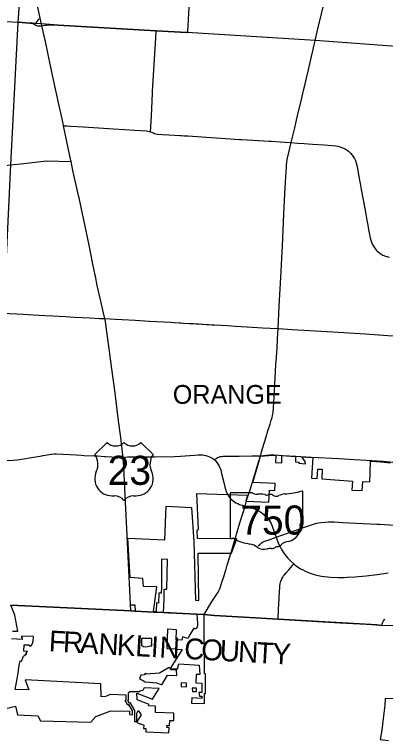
# Model space of a CAD drawing. Extents: x 1729596 to 1925846, y 659247 to 911751.
# Drawn here: x 1818365 to 1836127, y 772469 to 807237 of the extents above; entities that cross this region are included whole.
import ezdxf

# ---------------------------------------------------------------- set-up
doc = ezdxf.new("R2010")
doc.units = 0
for name, color, linetype in [('GM_X_Adjacent_County_Text', 7, 'Continuous'), ('GM_X_City_Street', 7, 'Continuous'), ('GM_X_Corporation', 7, 'Continuous'), ('GM_X_County', 7, 'Continuous'), ('GM_X_County_Road', 7, 'Continuous'), ('GM_X_State_Route', 7, 'Continuous'), ('GM_X_State_Shield', 7, 'Continuous'), ('GM_X_Township', 7, 'Continuous'), ('GM_X_Township_Road', 7, 'Continuous'), ('GM_X_Township_Text', 7, 'Continuous'), ('GM_X_US_Route', 7, 'Continuous'), ('GM_X_US_Shield', 7, 'Continuous')]:
    doc.layers.add(name, color=color, linetype=linetype)

msp = doc.modelspace()

# ---------------------------------------------------------------- linework, layer by layer
at = {"layer": 'GM_X_City_Street'}
for points in [[(1829157, 782891), (1829157, 782893), (1829284, 783295), (1829370, 783578), (1829403, 783698)], [(1829403, 783698), (1829476, 783942)], [(1828738, 781474), (1828935, 782130), (1829157, 782891)], [(1830888, 782204), (1832249, 782689), (1832627, 782818), (1832829, 782872), (1833025, 782905), (1833227, 782932), (1833389, 782939), (1833673, 782939), (1834091, 782912), (1835705, 782831)], [(1835705, 782831), (1835839, 782824), (1836553, 782786), (1836955, 782764), (1837100, 782758), (1837765, 782732)], [(1830028, 781790), (1830127, 781875), (1830195, 781928), (1830278, 781977), (1830355, 782013), (1830512, 782069), (1830888, 782204)], [(1830981, 778275), (1830981, 778426), (1830998, 778636), (1831007, 778800), (1831013, 778930), (1831036, 779338), (1831048, 779591), (1831061, 779791), (1831069, 779893), (1831081, 779966), (1831097, 780033), (1831121, 780106), (1831168, 780218), (1831205, 780288), (1831244, 780348), (1831278, 780391), (1831372, 780495), (1831514, 780657), (1831665, 780837), (1831734, 780922)], [(1827440, 778500), (1827802, 779087), (1828113, 779577), (1828183, 779692), (1828216, 779780), (1828313, 780101), (1828381, 780311), (1828487, 780643), (1828494, 780666)], [(1823936, 778682), (1823966, 778677), (1824145, 778671)], [(1825505, 778597), (1825506, 778597), (1825736, 778586), (1825825, 778586), (1826422, 778555), (1827074, 778521)], [(1827074, 778521), (1827092, 778520), (1827440, 778500)], [(1827440, 778500), (1827947, 778461), (1830173, 778324)], [(1830173, 778324), (1830981, 778275), (1833959, 778105)], [(1835956, 777979), (1835975, 778062), (1835994, 778131), (1836010, 778170), (1836027, 778201), (1836056, 778247), (1836092, 778281)], [(1833959, 778105), (1834906, 778051)], [(1834906, 778051), (1835221, 778034)], [(1835221, 778034), (1835694, 778007)], [(1835694, 778007), (1835717, 778005), (1835956, 777979)]]:
    msp.add_lwpolyline(points, dxfattribs=at)
at = {"layer": 'GM_X_Corporation'}
for points in [[(1818267, 777712), (1818526, 777699), (1818382, 778477), (1818182, 778957), (1823932, 778674), (1823918, 778971), (1824127, 778960), (1824141, 778666), (1825025, 778622), (1825481, 778599), (1825506, 778597), (1825523, 779224), (1825533, 779720), (1825651, 779713), (1825692, 781132), (1825397, 781147), (1825395, 779815), (1825387, 779525), (1825271, 779527), (1825258, 779053), (1825157, 779059), (1825145, 778634), (1825026, 778639), (1825182, 779821), (1824534, 779849), (1824515, 780220), (1823897, 780274), (1823795, 782165), (1825564, 782072), (1825620, 783690), (1826843, 783626), (1826946, 782000), (1827027, 779186), (1827198, 779170), (1827151, 781435), (1828757, 781433), (1829006, 782129), (1827128, 782148), (1827107, 782565), (1827182, 782566), (1827094, 784298), (1829525, 784216), (1829446, 783938), (1830547, 783879), (1830576, 784449), (1830831, 784435), (1830843, 784770), (1829780, 784830), (1830014, 785633), (1830149, 786086), (1830738, 786138), (1830880, 786128), (1830868, 785781), (1831158, 785769), (1831166, 786112), (1831819, 786077), (1831815, 785806), (1831974, 785799), (1831974, 785747), (1832303, 785711), (1832283, 785826), (1832129, 786061), (1832652, 786025), (1832587, 785037), (1832862, 785017), (1832886, 785468), (1833103, 785455), (1833079, 785005), (1834553, 784895), (1834518, 784462), (1835014, 784440), (1835039, 784870), (1835370, 784853), (1835392, 785285), (1835406, 785847), (1835905, 785817), (1836363, 785772)], [(1817968, 774000), (1818411, 774114), (1818508, 773703), (1819478, 773652), (1819605, 773412), (1822027, 773351), (1822253, 773619), (1822982, 773891), (1823867, 773865), (1823869, 773706), (1824013, 773704), (1824009, 773883), (1823832, 774190), (1823788, 774165), (1823663, 774381), (1823707, 774406), (1823707, 774642), (1822967, 774677), (1822717, 774575), (1822517, 774567), (1822492, 775187), (1818880, 775374), (1819053, 774896), (1818404, 774908), (1818486, 775425), (1818535, 775710), (1818583, 776065), (1818636, 776280), (1818700, 776269), (1818798, 776499), (1818958, 776635), (1818908, 776636), (1818992, 776737), (1818809, 776740), (1818820, 777055), (1819068, 777042), (1819068, 777007), (1819165, 777003), (1819223, 777108), (1819253, 777229), (1819268, 777456), (1818703, 777466), (1818702, 777396), (1818737, 777395), (1818738, 777311), (1818223, 777335)], [(1836587, 774459), (1836117, 774478), (1836103, 774163), (1836034, 773645), (1835958, 772968), (1835872, 772517), (1836265, 772469)]]:
    msp.add_lwpolyline(points, dxfattribs=at)
for points in [[(1824345, 775442), (1824627, 775281), (1825175, 775235), (1825413, 775126), (1825685, 775591), (1826129, 775580), (1826126, 775849), (1825830, 775846), (1825867, 775906), (1826173, 775897), (1826228, 776137), (1827210, 776079), (1827238, 775627), (1827055, 775635), (1827043, 775226), (1827330, 775211), (1827337, 774761), (1827196, 774766), (1827218, 774598), (1827327, 774593), (1827332, 774484), (1826851, 774504), (1826841, 774261), (1827466, 774237), (1827464, 774716), (1827514, 774716), (1827510, 775666), (1827460, 775665), (1827440, 778500), (1827098, 778520), (1827121, 778076), (1827120, 777980), (1827107, 777918), (1827081, 777867), (1827042, 777801), (1826956, 777852), (1826782, 777559), (1826660, 777355), (1826409, 777430), (1826380, 777271), (1826098, 777288), (1826124, 777772), (1825694, 777807), (1825650, 776871), (1826109, 776852), (1826109, 776842), (1826395, 776822), (1825819, 775914), (1825776, 775965), (1825313, 775697), (1824665, 775637), (1824635, 775689), (1824578, 775607), (1824414, 775592)], [(1824442, 777348), (1824442, 777026), (1824494, 776994), (1824548, 776966), (1824656, 776953), (1824740, 776974), (1824853, 776996), (1824934, 777003), (1824934, 777124), (1824922, 777124), (1824922, 777172), (1824942, 777172), (1824942, 777248), (1824942, 777348)], [(1826345, 775056), (1826603, 775041), (1826601, 775212), (1826347, 775231)], [(1823775, 774388), (1823850, 774258), (1823893, 774283), (1824116, 773897), (1824117, 773370), (1824217, 773370), (1824216, 773770), (1824292, 773900), (1824434, 773692), (1824210, 773349), (1824358, 773262), (1824368, 773274), (1824549, 773200), (1824547, 773047), (1824647, 773046), (1824645, 772890), (1825759, 772839), (1825774, 773090), (1825665, 773097), (1825671, 773197), (1825780, 773190), (1825795, 773428), (1825995, 773423), (1825999, 773780), (1825120, 773801), (1825121, 774119), (1824773, 774122), (1824817, 774196), (1824236, 774422), (1824220, 774734), (1824970, 774444), (1825290, 774965), (1824574, 774985), (1824507, 774863), (1824348, 774835), (1824349, 774792), (1823893, 774792), (1823807, 774742), (1823807, 774406)], [(1826873, 774982), (1826880, 774820), (1827079, 774810), (1827071, 774971)]]:
    msp.add_lwpolyline(points, close=True, dxfattribs=at)
at = {"layer": 'GM_X_County'}
msp.add_lwpolyline([(1836651, 777955), (1835956, 777979), (1835717, 778005), (1830981, 778275), (1827947, 778461), (1827440, 778500), (1827092, 778520), (1826422, 778555), (1825825, 778586), (1825736, 778586), (1825506, 778597), (1825481, 778599), (1825025, 778622), (1824141, 778666), (1823966, 778677), (1823936, 778682), (1818187, 778957)], dxfattribs=at)
at = {"layer": 'GM_X_County_Road'}
for points in [[(1797153, 808138), (1797813, 808094), (1798478, 808064), (1798746, 808039), (1801838, 807850), (1803855, 807737), (1803954, 807731), (1804251, 807713), (1804397, 807702), (1804736, 807682), (1805136, 807661), (1806811, 807563), (1808119, 807486), (1809547, 807399), (1810973, 807310), (1811477, 807276), (1812106, 807251), (1812390, 807244), (1812704, 807223), (1813792, 807154), (1815652, 807028), (1817412, 806933), (1818544, 806864), (1818913, 806840)], [(1832766, 805999), (1832958, 806827), (1832968, 806868), (1833153, 807676)], [(1818913, 806840), (1819101, 806829), (1819232, 806820), (1819275, 806791), (1819333, 806753), (1819390, 806722), (1819467, 806700), (1819559, 806690), (1819676, 806703)], [(1831618, 801105), (1831725, 801561), (1831782, 801810), (1831838, 802029), (1831953, 802532), (1832071, 803028), (1832169, 803448), (1832199, 803580), (1832422, 804522), (1832586, 805234), (1832650, 805492), (1832684, 805641), (1832763, 805986), (1832766, 805999)], [(1820717, 801905), (1820738, 801905), (1820881, 801901), (1821048, 801890), (1821670, 801851), (1823103, 801757), (1823630, 801723), (1824118, 801695), (1824691, 801661), (1824752, 801655), (1824814, 801642), (1824880, 801622), (1824978, 801581), (1825016, 801565), (1825065, 801542), (1825127, 801522), (1825213, 801507), (1825442, 801493), (1825753, 801476), (1826274, 801446), (1826357, 801438), (1826504, 801432), (1826669, 801422), (1829143, 801256), (1829167, 801255), (1829247, 801250), (1830557, 801174), (1830565, 801173), (1830661, 801169), (1831088, 801139), (1831565, 801111), (1831618, 801105)], [(1830137, 786102), (1830243, 786458), (1830418, 787013), (1830501, 787304), (1830611, 787617), (1830657, 787812), (1830695, 787936), (1830724, 788026), (1830738, 788091), (1830747, 788159), (1830783, 788662), (1830811, 789171), (1830832, 789527), (1830864, 790126), (1830879, 790499), (1830888, 790614), (1830935, 791259), (1830959, 791695), (1830989, 792193), (1831044, 793262), (1831126, 794929), (1831177, 795880), (1831189, 796127), (1831208, 796535), (1831224, 796892), (1831260, 797697), (1831329, 798960), (1831359, 799467), (1831386, 799918), (1831394, 800046), (1831401, 800130), (1831406, 800170), (1831427, 800290), (1831618, 801105)], [(1831618, 801105), (1831914, 801083), (1832241, 801060), (1832630, 801030), (1833198, 800989), (1833568, 800963), (1833750, 800945), (1833841, 800929), (1833953, 800901), (1833994, 800888), (1834075, 800856), (1834194, 800797), (1834287, 800738), (1834352, 800690), (1834449, 800601), (1834514, 800523), (1834576, 800442), (1834637, 800335), (1834686, 800241), (1834720, 800133), (1834770, 799952), (1834842, 799561), (1834917, 799142), (1834969, 798857), (1835136, 797945), (1835185, 797674), (1835238, 797383), (1835280, 797146), (1835320, 796934), (1835392, 796543), (1835422, 796431), (1835496, 796238), (1835581, 796090), (1835702, 795941), (1835860, 795804), (1836005, 795717), (1836126, 795665), (1836296, 795616)], [(1814566, 799659), (1814662, 799670), (1814940, 799695), (1815216, 799728), (1816018, 799800), (1816744, 799881), (1817764, 799993), (1818194, 800042), (1818804, 800110)], [(1818804, 800110), (1819351, 800171), (1819913, 800231), (1821077, 800198)], [(1830137, 786102), (1830408, 786127), (1830473, 786131), (1830595, 786143), (1830674, 786150), (1830727, 786150), (1830805, 786149), (1831205, 786125), (1831840, 786089), (1832575, 786043), (1833895, 785967), (1834638, 785924), (1835200, 785890), (1836012, 785840), (1836343, 785821), (1836473, 785802), (1836589, 785781), (1836648, 785764), (1836710, 785745), (1836767, 785724)], [(1827933, 785912), (1827967, 785947), (1828014, 785981), (1828077, 786017), (1828143, 786045), (1828212, 786066), (1828234, 786070), (1828276, 786074), (1828349, 786080), (1828458, 786082), (1829120, 786088), (1829721, 786095), (1830137, 786102)], [(1829476, 783942), (1829480, 783955), (1829642, 784477), (1829865, 785207), (1829995, 785632), (1830137, 786102)], [(1828494, 780666), (1828554, 780858), (1828738, 781474)]]:
    msp.add_lwpolyline(points, dxfattribs=at)
at = {"layer": 'GM_X_State_Route'}
for points in [[(1815949, 786077), (1816340, 786036), (1817421, 785936), (1817504, 785931), (1817524, 785929), (1818089, 785876), (1818484, 785913), (1818908, 785967), (1819089, 785999), (1819665, 786100), (1819718, 786112), (1820036, 786168), (1820128, 786185), (1820241, 786200), (1820367, 786198), (1820698, 786179), (1821320, 786143), (1821549, 786130)], [(1821549, 786130), (1821693, 786122), (1822187, 786100), (1822334, 786095)], [(1823563, 786025), (1823628, 786033), (1823775, 786046), (1823922, 786053), (1824581, 786061), (1825105, 786055), (1826030, 786067), (1826319, 786087), (1826985, 786136), (1827143, 786145), (1827249, 786149), (1827367, 786145), (1827524, 786120), (1827661, 786077), (1827737, 786044), (1827810, 786003), (1827879, 785955), (1827933, 785912), (1827993, 785854), (1828049, 785790), (1828123, 785685), (1828168, 785604), (1828202, 785526), (1828238, 785425), (1828282, 785261), (1828387, 784818), (1828437, 784614), (1828504, 784396), (1828565, 784270)], [(1822334, 786095), (1822671, 786075), (1822720, 786071), (1823334, 786043), (1823500, 786028), (1823563, 786025)], [(1828565, 784270), (1828569, 784262), (1828604, 784194), (1828648, 784129), (1828708, 784059), (1828761, 784007), (1828819, 783958), (1828895, 783902), (1828967, 783858), (1829063, 783811), (1829136, 783778), (1829258, 783733), (1829403, 783698)], [(1829403, 783698), (1829636, 783627), (1829774, 783588), (1829890, 783548), (1830017, 783494), (1830110, 783438), (1830211, 783374), (1830305, 783298), (1830422, 783188), (1830516, 783076), (1830564, 783014), (1830648, 782859), (1830699, 782739), (1830797, 782459), (1830888, 782204), (1831011, 781894), (1831061, 781782), (1831130, 781649), (1831230, 781480), (1831303, 781382), (1831449, 781200), (1831590, 781057), (1831734, 780922), (1831852, 780832), (1832062, 780696), (1832163, 780638), (1832275, 780576), (1832437, 780506), (1832565, 780463), (1832716, 780413), (1832906, 780365), (1833062, 780340), (1833344, 780306), (1833500, 780298), (1833859, 780281), (1834130, 780274), (1834309, 780283), (1834652, 780302), (1835197, 780361), (1835722, 780425), (1836249, 780492)]]:
    msp.add_lwpolyline(points, dxfattribs=at)
at = {"layer": 'GM_X_State_Shield'}
for p, q in [((1832171, 783277), (1832171, 784383)), ((1832171, 783277), (1832171, 784383)), ((1828691, 784294), (1828691, 782181)), ((1828691, 784294), (1828691, 782181)), ((1829744, 784330), (1828725, 784330)), ((1829744, 784330), (1828725, 784330)), ((1832171, 783277), (1832171, 783277)), ((1832171, 783277), (1832171, 783277))]:
    msp.add_line(p, q, dxfattribs=at)
for centre, major_axis, start_param, end_param in [((1830931, 787211), (3691, 0), 4.814394, 5.042369), ((1830931, 787211), (3691, 0), 4.814394, 5.042369), ((1832132, 784387), (38.7, 0), 6.141152, 7.989035), ((1832132, 784387), (38.7, 0), 6.141152, 7.989035), ((1828730, 784298), (40.3, 0), 1.712693, 3.28349), ((1828730, 784298), (40.3, 0), 1.712693, 3.28349), ((1829987, 784576), (391, 0), 4.042523, 4.731795), ((1829987, 784576), (391, 0), 4.042523, 4.731795), ((1830116, 783144), (1404, 0), 1.404758, 1.657858), ((1830116, 783144), (1404, 0), 1.404758, 1.657858), ((1830435, 784309), (113, 0), 3.836095, 5.185415), ((1830435, 784309), (113, 0), 3.836095, 5.185415), ((1830601, 784065), (235, 0), 0.950623, 2.079405), ((1830601, 784065), (235, 0), 0.950623, 2.079405), ((1830904, 784400), (282, 0), 4.081561, 5.145723), ((1830904, 784400), (282, 0), 4.081561, 5.145723), ((1831402, 783685), (743, 0), 1.699011, 2.107814), ((1831402, 783685), (743, 0), 1.699011, 2.107814), ((1832162, 783196), (60, 0), 1.883978, 3.671073), ((1832162, 783196), (60, 0), 1.883978, 3.671073), ((1831781, 783056), (360, 0), 5.934695, 6.695948), ((1831781, 783056), (360, 0), 5.934695, 6.695948), ((1832130, 783273), (41.5, 0), 5.05454, 6.418171), ((1832130, 783273), (41.5, 0), 5.05454, 6.418171), ((1831138, 782674), (923, 0), 5.101752, 6.440018), ((1831138, 782674), (923, 0), 5.101752, 6.440018), ((1832310, 782815), (262, 0), 2.387724, 3.262537), ((1832310, 782815), (262, 0), 2.387724, 3.262537), ((1828731, 782176), (40.7, 0), 3.00124, 4.508301), ((1828731, 782176), (40.7, 0), 3.00124, 4.508301), ((1828737, 782392), (310, 0), 4.665946, 4.897461), ((1828737, 782392), (310, 0), 4.665946, 4.897461), ((1828800, 782059), (112, 0), 0.519207, 1.627899), ((1828800, 782059), (112, 0), 0.519207, 1.627899), ((1830214, 783957), (2665, 0), 4.195997, 4.488961), ((1830214, 783957), (2665, 0), 4.195997, 4.488961), ((1831527, 781587), (506, 0), 1.647645, 2.488434), ((1831527, 781587), (506, 0), 1.647645, 2.488434), ((1829419, 781231), (834, 0), 0.823519, 1.323587), ((1829419, 781231), (834, 0), 0.823519, 1.323587), ((1830321, 782048), (529, 0), 4.026481, 4.996735), ((1830321, 782048), (529, 0), 4.026481, 4.996735), ((1830627, 781318), (435, 0), 1.495662, 1.94098), ((1830627, 781318), (435, 0), 1.495662, 1.94098), ((1830665, 781890), (282, 0), 4.691044, 5.507374), ((1830665, 781890), (282, 0), 4.691044, 5.507374), ((1830920, 781685), (79.4, 0), 1.147584, 2.315152), ((1830920, 781685), (79.4, 0), 1.147584, 2.315152), ((1830887, 781976), (298, 0), 4.937069, 5.64225), ((1830887, 781976), (298, 0), 4.937069, 5.64225)]:
    msp.add_ellipse(centre, major_axis=major_axis, ratio=0.8, start_param=start_param, end_param=end_param, dxfattribs=at)
at = {"layer": 'GM_X_Township'}
for points in [[(1845296, 807619), (1845145, 805182), (1843287, 805303), (1843103, 805315), (1843041, 805313), (1842837, 805328), (1840812, 805456), (1837716, 805633), (1832763, 805986), (1831742, 806059), (1826634, 806376), (1826602, 806370), (1825150, 806460), (1820453, 806733), (1819657, 806793), (1819325, 806814), (1819232, 806820), (1819101, 806829), (1818544, 806864), (1818726, 809558)], [(1817250, 778977), (1817281, 779754), (1817338, 781221), (1817524, 785929), (1817856, 792932), (1818194, 800042), (1818544, 806864)]]:
    msp.add_lwpolyline(points, dxfattribs=at)
at = {"layer": 'GM_X_Township_Road'}
for points in [[(1826634, 806376), (1826663, 806429), (1826736, 807853), (1826739, 807902), (1826741, 807936), (1826878, 810126), (1826891, 810353), (1826913, 810774), (1826943, 811293)], [(1819232, 806820), (1819325, 806814), (1819371, 806824), (1819399, 806846), (1819491, 806962), (1819552, 807038)], [(1819676, 806703), (1819803, 806721), (1819894, 806734), (1820004, 806746), (1820092, 806749), (1820453, 806733), (1825150, 806460), (1826602, 806370), (1826634, 806376)], [(1824880, 801622), (1824918, 802376), (1824972, 803474), (1824977, 803552), (1825131, 806119), (1825150, 806460)], [(1817878, 792931), (1817995, 792928), (1818106, 792923), (1818482, 792901), (1818787, 792885), (1819262, 792857), (1819834, 792826), (1820206, 792804), (1820486, 792789), (1820816, 792770), (1821218, 792749), (1821979, 792708), (1822434, 792685), (1822684, 792674)], [(1822684, 792674), (1823205, 792644), (1823518, 792626), (1824136, 792597), (1824824, 792554), (1825845, 792496), (1826005, 792489), (1826266, 792474), (1826340, 792468)], [(1826340, 792468), (1826440, 792462), (1826727, 792446), (1826941, 792432), (1827053, 792426), (1827196, 792418), (1827337, 792408), (1827375, 792407), (1827561, 792395), (1827672, 792389), (1827796, 792381), (1827938, 792372), (1828578, 792339), (1828925, 792317), (1829210, 792298), (1829505, 792285), (1830238, 792237), (1830989, 792193)], [(1830989, 792193), (1830989, 792193), (1831659, 792153), (1833599, 792034), (1835168, 791938), (1836243, 791862), (1837317, 791801), (1838966, 791703), (1839258, 791696)], [(1824145, 778671), (1824181, 778670), (1825025, 778622), (1825481, 778599), (1825505, 778597)]]:
    msp.add_lwpolyline(points, dxfattribs=at)
at = {"layer": 'GM_X_US_Route'}
for points in [[(1819598, 807070), (1819046, 809639), (1818948, 810127), (1818889, 810378), (1818800, 810798), (1818772, 810948)], [(1819959, 805403), (1819958, 805406), (1819845, 805945), (1819676, 806703), (1819657, 806793), (1819598, 807070)], [(1820693, 802007), (1820673, 802094), (1820517, 802807), (1820343, 803596), (1820201, 804258), (1819959, 805403)], [(1821066, 800249), (1820717, 801905), (1820693, 802007)], [(1821461, 798452), (1821449, 798511), (1821155, 799766), (1821077, 800198), (1821066, 800249)], [(1823552, 786128), (1823460, 786981), (1823349, 787775), (1823161, 789237), (1823026, 790261), (1822930, 790991), (1822896, 791248), (1822775, 792154), (1822731, 792433), (1822700, 792611), (1822684, 792674), (1822657, 792813), (1822450, 793722), (1822328, 794267), (1822235, 794713), (1822226, 794758), (1822121, 795276), (1821937, 796186), (1821679, 797401), (1821619, 797688), (1821461, 798452)], [(1823558, 786077), (1823552, 786128)], [(1823563, 786025), (1823558, 786077)], [(1823936, 778682), (1823645, 784547), (1823597, 785555), (1823580, 785831), (1823563, 786025)]]:
    msp.add_lwpolyline(points, dxfattribs=at)
at = {"layer": 'GM_X_US_Shield'}
for p, q in [((1822794, 786741), (1822214, 786161)), ((1822794, 786741), (1822214, 786161)), ((1824998, 786161), (1824418, 786741)), ((1824998, 786161), (1824418, 786741)), ((1823026, 784189), (1823142, 784189)), ((1823026, 784189), (1823142, 784189)), ((1824070, 784189), (1824186, 784189)), ((1824070, 784189), (1824186, 784189))]:
    msp.add_line(p, q, dxfattribs=at)
for centre, radius, start, end in [((1823200, 787155), 580, 225.573, 314.427), ((1823200, 787155), 580, 225.573, 314.427), ((1824012, 787155), 580, 225.573, 314.427), ((1824012, 787155), 580, 225.573, 314.427), ((1821549, 785695), 812, 334.5471, 35.0009), ((1821549, 785695), 812, 334.5471, 35.0009), ((1825663, 785695), 812, 144.9991, 205.4529), ((1825663, 785695), 812, 144.9991, 205.4529), ((1823017, 785001), 812, 154.8319, 270.6383), ((1823017, 785001), 812, 154.8319, 270.6383), ((1824195, 785001), 812, 269.3617, 25.1681), ((1824195, 785001), 812, 269.3617, 25.1681), ((1823142, 783609), 580, 36.8699, 90), ((1823142, 783609), 580, 36.8699, 90), ((1824070, 783609), 580, 90, 143.1301), ((1824070, 783609), 580, 90, 143.1301)]:
    msp.add_arc(centre, radius, start, end, dxfattribs=at)

# ---------------------------------------------------------------- texts
at = {"layer": 'GM_X_Adjacent_County_Text'}
for s, rotation, p in [('F', 356.8079, (1819990, 776742)), ('R', 356.8077, (1820666, 776705)), ('A', 356.8076, (1821479, 776659)), ('N', 356.8079, (1822362, 776610)), ('K', 356.8079, (1823245, 776561)), ('L', 356.8078, (1824128, 776511)), ('I', 356.8075, (1824875, 776470)), ('N', 356.8076, (1825284, 776447)), ('C', 356.8078, (1826470, 776381)), ('O', 356.8074, (1827283, 776336)), ('U', 356.8087, (1828166, 776286)), ('N', 356.8166, (1829049, 776237)), ('T', 356.8443, (1829932, 776188)), ('Y', 356.9671, (1830682, 776147))]:
    msp.add_text(s, height=1000, rotation=rotation, dxfattribs=at).set_placement(p)
at = {"layer": 'GM_X_State_Shield'}
msp.add_text('750', height=1392.2, dxfattribs=at).set_placement((1829180, 782330))
msp.add_text('750', height=1392.2, dxfattribs=at).set_placement((1829180, 782330))
at = {"layer": 'GM_X_Township_Text'}
msp.add_text('ORANGE', height=900, rotation=0, dxfattribs=at).set_placement((1825944, 788593))
at = {"layer": 'GM_X_US_Shield'}
msp.add_text('23', height=1392.2, dxfattribs=at).set_placement((1822831, 784711))
msp.add_text('23', height=1392.2, dxfattribs=at).set_placement((1822831, 784711))

doc.saveas('drawing.dxf')
